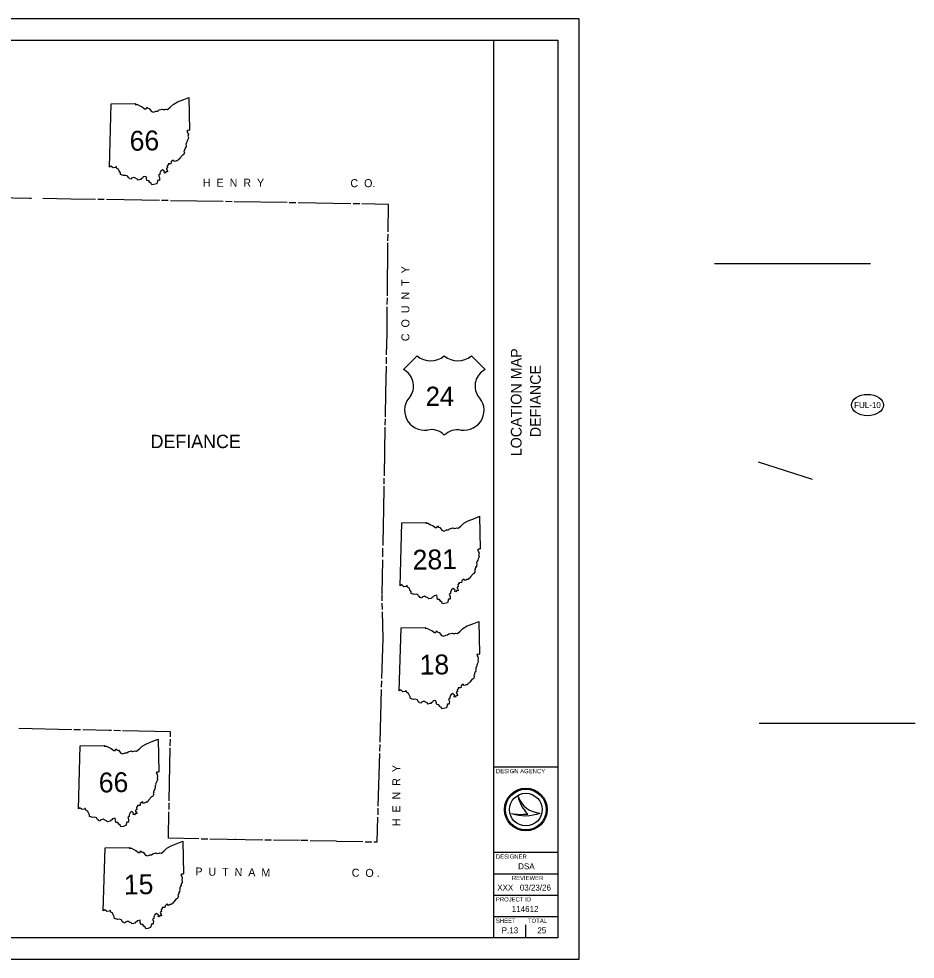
# Model space of a CAD drawing. Extents: x 0 to 419, y 0 to 220.
# Drawn here: x 208.9 to 418.6, y 0 to 220 of the extents above; entities that cross this region are included whole.
import ezdxf

# ---------------------------------------------------------------- set-up
doc = ezdxf.new("R2010")
doc.units = 0
for name, color, linetype in [('GM_X_County', 7, 'Continuous'), ('Level 12', 7, 'Continuous'), ('Level 13', 7, 'Continuous'), ('PV_P_Text', 7, 'Continuous'), ('SH_Border', 7, 'Continuous'), ('SH_Cut_Line', 7, 'Continuous'), ('SH_Data', 7, 'Continuous'), ('SH_Text', 7, 'Continuous')]:
    doc.layers.add(name, color=color, linetype=linetype)

msp = doc.modelspace()

# ---------------------------------------------------------------- linework, layer by layer
at = {"layer": 'GM_X_County'}
for points in [[(211.47, 178), (199.55, 178.2)], [(211.9, 177.99), (211.47, 178)], [(221.09, 177.84), (214.48, 177.95)], [(226.84, 177.74), (221.09, 177.84)], [(228.9, 177.71), (227.36, 177.73)], [(241.78, 177.49), (229.42, 177.7)], [(243.84, 177.46), (242.29, 177.48)], [(256.71, 177.24), (244.36, 177.45)], [(258.78, 177.2), (257.23, 177.23)], [(271.65, 176.99), (259.29, 177.19)], [(273.71, 176.95), (272.16, 176.98)], [(286.58, 176.74), (274.23, 176.94)], [(288.65, 176.7), (287.1, 176.73)], [(295.34, 176.59), (289.16, 176.69)], [(295.27, 170.15), (295.34, 176.59)], [(295.25, 168.08), (295.27, 169.63)], [(295.12, 155.21), (295.25, 167.56)], [(295.1, 153.14), (295.12, 154.69)], [(295.03, 146.45), (295.09, 152.63)], [(294.93, 141.35), (295.03, 146.45)], [(294.9, 139.28), (294.92, 140.83)], [(294.77, 132.59), (294.89, 138.77)], [(294.66, 126.87), (294.77, 132.59)], [(294.63, 124.96), (294.65, 126.39)], [(294.4, 113.05), (294.62, 124.48)], [(294.36, 111.14), (294.39, 112.57)], [(294.25, 104.94), (294.35, 110.66)], [(294.18, 101.71), (294.25, 104.94)], [(294.09, 96.81), (294.18, 101.71)], [(294.04, 94.1), (294.08, 96.14)], [(293.87, 85.29), (294.03, 93.42)], [(293.9, 83.84), (293.87, 85.17)], [(293.95, 81.78), (293.91, 83.33)], [(294.1, 75.08), (293.96, 81.26)], [(293.83, 65.68), (294.1, 75.08)], [(293.77, 63.61), (293.82, 65.16)], [(293.41, 50.74), (293.76, 63.1)], [(221.27, 53.69), (208.91, 53.94)], [(223.33, 53.65), (221.78, 53.68)], [(230.02, 53.52), (223.85, 53.64)], [(230.6, 53.5), (230.02, 53.52)], [(232.66, 53.45), (231.12, 53.49)], [(244.36, 52.02), (244.38, 53.17), (233.18, 53.44)], [(244.32, 49.95), (244.35, 51.5)], [(244.07, 37.08), (244.31, 49.44)], [(293.35, 48.68), (293.39, 50.23)], [(292.98, 35.81), (293.34, 48.16)], [(244.03, 35.02), (244.06, 36.57)], [(292.92, 33.75), (292.97, 35.3)], [(243.91, 28.33), (244.02, 34.5)], [(292.75, 27.44), (292.91, 33.23)], [(251.02, 28.12), (243.91, 28.33)], [(253.08, 28.08), (251.75, 28.1), (251.53, 28.1)], [(265.95, 27.88), (253.6, 28.07)], [(259.51, 28.14), (259.51, 27.98)], [(268, 27.87), (267.69, 27.87), (267.69, 27.86), (266.47, 27.87)], [(274.69, 27.76), (268.51, 27.86)], [(276.5, 27.73), (274.95, 27.76)], [(283.19, 27.63), (277.02, 27.72)], [(283.2, 27.63), (289.38, 27.5)], [(289.89, 27.49), (291.44, 27.46)], [(291.96, 27.45), (292.72, 27.43)]]:
    msp.add_lwpolyline(points, dxfattribs=at)
at = {"layer": 'Level 12'}
for p, q in [((371.6, 162.77), (408.13, 162.77)), ((382.05, 55.19), (418.58, 55.19))]:
    msp.add_line(p, q, dxfattribs=at)
at = {"layer": 'Level 13'}
msp.add_line((394.56, 112.19), (381.94, 116.3), dxfattribs=at)
msp.add_ellipse((407.43, 129.63), major_axis=(3.75, 0), ratio=0.666667, dxfattribs=at)
at = {"layer": 'PV_P_Text'}
for p, q in [((302.08, 141.12), (298.89, 137.92)), ((317.96, 137.92), (314.77, 141.12))]:
    msp.add_line(p, q, dxfattribs=at)
for centre, radius, start, end in [((305.25, 145.15), 5.13, 231.813, 308.187), ((311.59, 145.15), 5.13, 231.813, 308.187), ((296.9, 134.07), 4.34, 329.1175, 62.6108), ((319.95, 134.07), 4.34, 117.3892, 210.8825), ((303.81, 128.42), 4.68, 133.0046, 278.7282), ((313.04, 128.42), 4.68, 261.2718, 46.9954), ((305.38, 119.7), 4.19, 43.4177, 101.8742), ((311.55, 119.42), 4.44, 79.9613, 134.7468)]:
    msp.add_arc(centre, radius, start, end, dxfattribs=at)
at = {"layer": 'SH_Border'}
for p, q in [((320, 5), (320, 215)), ((320, 45), (335, 45)), ((320, 25), (335, 25)), ((320, 20), (335, 20)), ((320, 15), (335, 15)), ((320, 10), (335, 10))]:
    msp.add_line(p, q, dxfattribs=at)
msp.add_lwpolyline([(15, 215), (335, 215), (335, 5), (15, 5)], close=True, dxfattribs=at)
at = {"layer": 'SH_Cut_Line'}
msp.add_lwpolyline([(0, 0), (340, 0), (340, 220), (0, 220)], close=True, dxfattribs=at)
at = {"layer": 'SH_Data'}
for p, q in [((325.67, 38.1), (325.67, 38.1)), ((324.17, 34.1), (324.17, 34.1)), ((327.5, 35), (327.5, 35)), ((330.87, 34.19), (330.87, 34.19)), ((323.75, 6.75), (323.75, 6.75)), ((327.5, 5), (327.5, 8))]:
    msp.add_line(p, q, dxfattribs=at)
for radius in [5, 4.77, 4.77, 3.82]:
    msp.add_circle((327.5, 35), radius, dxfattribs=at)
for centre, radius, start, end in [((331.16, 39.98), 5.8, 198.9257, 198.9319), ((333.47, 39.7), 7.96, 191.6379, 191.6421), ((331.16, 39.98), 5.8, 198.9319, 267.1657), ((333.47, 39.7), 7.96, 191.6421, 226.0947), ((327.39, 43.7), 10.13, 251.4576, 290.0832), ((326.48, 46.54), 12.66, 259.4964, 259.4995), ((327.39, 43.7), 10.13, 251.4527, 251.4576), ((326.48, 46.54), 12.66, 259.4995, 276.6672)]:
    msp.add_arc(centre, radius, start, end, dxfattribs=at)
at = {"layer": 'SH_Text'}
for p, q in [((230.08, 185.33), (230.49, 200.07)), ((298.07, 87.35), (298.48, 102.09)), ((297.89, 62.76), (298.3, 77.49)), ((222.86, 35.2), (223.27, 49.93)), ((228.66, 11.33), (229.07, 26.07))]:
    msp.add_line(p, q, dxfattribs=at)
for points in [[(230.49, 200.07), (236.21, 200.17), (236.12, 199.99), (236.66, 199.95), (237.23, 199.63), (237.72, 199.44), (238.31, 198.97), (238.67, 198.97), (238.82, 199.36), (239.09, 199.06), (239.41, 199.01), (239.97, 198.3), (240.43, 198.15), (240.98, 198.39), (241.39, 198.43), (241.69, 198.67), (242.48, 198.87), (242.69, 198.75), (243.11, 198.78), (243.32, 198.87), (243.68, 198.79), (244.32, 199.32), (244.98, 199.95), (245.99, 200.55), (247.49, 201.11), (248.69, 201.62), (248.86, 193.97)], [(248.86, 193.97), (248.68, 193.86), (248.41, 193.92), (248.22, 193.7), (248.45, 193.34), (248.56, 192.96), (248.46, 192.55), (248.56, 192.2), (248.49, 191.92), (248.32, 191.63), (248.26, 191.36), (248.12, 191.07), (248.13, 190.91), (247.99, 190.78), (248.01, 190.3), (247.94, 190.04), (247.97, 189.81), (247.74, 189.75), (247.79, 189.56), (247.65, 189.41), (247.68, 189.16), (247.52, 189), (247.68, 188.68), (247.55, 188.58), (247.44, 188.19), (247.15, 188.11), (246.57, 187.4), (246.37, 187.13), (246.14, 187.06), (246.01, 186.78), (245.72, 186.78), (245.3, 186.59), (245.02, 186.92), (244.53, 186.52), (244.47, 186.06), (243.86, 186.08), (243.88, 185.85), (243.75, 185.78), (243.62, 185.55), (243.69, 185.13), (243.41, 185.03), (243.44, 184.79), (243.63, 184.64), (243.71, 184.18), (243.4, 184.27), (243.15, 183.89), (242.89, 183.98), (242.98, 184.31), (242.54, 184.7), (242.13, 184.38), (241.91, 183.88), (241.91, 183.54), (241.61, 183.34), (241.8, 182.86), (241.77, 182.53), (241.77, 182.21), (241.39, 182.22), (241.16, 181.38)], [(241.16, 181.38), (240.49, 181.22), (240.03, 181.12), (239.86, 181.5), (239.53, 181.71), (239.32, 182.09), (238.84, 182.15), (238.73, 182.68), (238.67, 183.11), (238.02, 183), (237.85, 182.74), (237.61, 182.67), (237.48, 182.4), (237.17, 182.38), (236.83, 182.25), (236.61, 182.52), (236.06, 182.78), (235.81, 182.91), (235.29, 182.7), (235.18, 182.45), (234.76, 182.56), (234.67, 182.84), (234.42, 182.92), (234.36, 183.22), (233.83, 183.37), (233.42, 183.31), (232.69, 183.55), (232.65, 183.93), (232.4, 184.4), (232.28, 184.73), (231.82, 184.98), (231.73, 185.37), (231.58, 185.36), (231.45, 185.2), (230.94, 185.13), (230.74, 185.29), (230.46, 185.56), (230.08, 185.33)], [(298.48, 102.09), (304.2, 102.19), (304.11, 102.01), (304.65, 101.97), (305.23, 101.65), (305.71, 101.46), (306.3, 100.99), (306.66, 100.99), (306.81, 101.38), (307.08, 101.08), (307.4, 101.03), (307.96, 100.32), (308.42, 100.17), (308.97, 100.41), (309.38, 100.45), (309.68, 100.69), (310.47, 100.89), (310.69, 100.77), (311.1, 100.8), (311.31, 100.89), (311.67, 100.81), (312.31, 101.34), (312.97, 101.97), (313.98, 102.57), (315.49, 103.13), (316.68, 103.64), (316.85, 95.99)], [(316.85, 95.99), (316.67, 95.89), (316.4, 95.94), (316.22, 95.72), (316.44, 95.36), (316.55, 94.99), (316.46, 94.57), (316.55, 94.22), (316.49, 93.94), (316.31, 93.65), (316.25, 93.38), (316.11, 93.09), (316.12, 92.93), (315.98, 92.8), (316.01, 92.32), (315.94, 92.06), (315.96, 91.83), (315.73, 91.77), (315.79, 91.58), (315.64, 91.44), (315.67, 91.18), (315.51, 91.02), (315.67, 90.7), (315.54, 90.6), (315.43, 90.21), (315.14, 90.13), (314.56, 89.42), (314.36, 89.15), (314.13, 89.08), (314, 88.8), (313.72, 88.8), (313.29, 88.61), (313.01, 88.94), (312.52, 88.54), (312.47, 88.08), (311.85, 88.1), (311.88, 87.87), (311.74, 87.8), (311.61, 87.57), (311.69, 87.15), (311.4, 87.05), (311.43, 86.81), (311.62, 86.66), (311.7, 86.2), (311.39, 86.29), (311.14, 85.91), (310.88, 86), (310.97, 86.33), (310.53, 86.72), (310.12, 86.4), (309.91, 85.9), (309.9, 85.56), (309.6, 85.36), (309.79, 84.88), (309.76, 84.55), (309.76, 84.23), (309.38, 84.24), (309.15, 83.4)], [(309.15, 83.4), (308.48, 83.24), (308.02, 83.14), (307.85, 83.52), (307.52, 83.73), (307.31, 84.11), (306.83, 84.17), (306.72, 84.7), (306.67, 85.13), (306.02, 85.02), (305.84, 84.76), (305.61, 84.69), (305.47, 84.42), (305.16, 84.4), (304.82, 84.28), (304.6, 84.54), (304.05, 84.8), (303.8, 84.93), (303.28, 84.72), (303.17, 84.47), (302.75, 84.58), (302.66, 84.86), (302.41, 84.94), (302.35, 85.24), (301.82, 85.39), (301.41, 85.33), (300.69, 85.57), (300.64, 85.95), (300.4, 86.42), (300.27, 86.75), (299.81, 87), (299.72, 87.39), (299.57, 87.38), (299.44, 87.22), (298.93, 87.15), (298.73, 87.31), (298.45, 87.58), (298.07, 87.35)], [(298.3, 77.49), (304.02, 77.59), (303.93, 77.41), (304.47, 77.37), (305.04, 77.06), (305.53, 76.86), (306.12, 76.39), (306.47, 76.4), (306.62, 76.78), (306.9, 76.48), (307.22, 76.43), (307.78, 75.73), (308.24, 75.57), (308.79, 75.81), (309.2, 75.85), (309.5, 76.09), (310.28, 76.3), (310.5, 76.18), (310.92, 76.2), (311.13, 76.29), (311.49, 76.21), (312.13, 76.75), (312.78, 77.38), (313.79, 77.97), (315.3, 78.54), (316.49, 79.04), (316.67, 71.4)], [(316.67, 71.4), (316.49, 71.29), (316.22, 71.34), (316.03, 71.12), (316.26, 70.77), (316.37, 70.39), (316.27, 69.97), (316.37, 69.63), (316.3, 69.34), (316.13, 69.05), (316.07, 68.78), (315.93, 68.49), (315.94, 68.33), (315.8, 68.21), (315.82, 67.73), (315.75, 67.46), (315.78, 67.23), (315.55, 67.17), (315.6, 66.98), (315.46, 66.84), (315.49, 66.59), (315.33, 66.43), (315.48, 66.11), (315.36, 66), (315.25, 65.61), (314.96, 65.54), (314.38, 64.82), (314.17, 64.55), (313.94, 64.48), (313.82, 64.21), (313.53, 64.21), (313.1, 64.01), (312.83, 64.35), (312.34, 63.95), (312.28, 63.49), (311.67, 63.5), (311.69, 63.27), (311.56, 63.2), (311.43, 62.97), (311.5, 62.56), (311.21, 62.45), (311.25, 62.21), (311.43, 62.06), (311.52, 61.6), (311.21, 61.7), (310.96, 61.31), (310.7, 61.4), (310.79, 61.73), (310.35, 62.12), (309.94, 61.81), (309.72, 61.3), (309.72, 60.96), (309.41, 60.76), (309.61, 60.28), (309.57, 59.95), (309.58, 59.64), (309.2, 59.65), (308.96, 58.8)], [(308.96, 58.8), (308.3, 58.64), (307.83, 58.54), (307.67, 58.93), (307.34, 59.13), (307.12, 59.52), (306.65, 59.57), (306.54, 60.1), (306.48, 60.53), (305.83, 60.43), (305.65, 60.16), (305.42, 60.09), (305.29, 59.83), (304.97, 59.8), (304.64, 59.68), (304.42, 59.94), (303.86, 60.2), (303.62, 60.34), (303.1, 60.13), (302.98, 59.88), (302.57, 59.99), (302.47, 60.26), (302.22, 60.35), (302.17, 60.64), (301.63, 60.8), (301.22, 60.73), (300.5, 60.97), (300.46, 61.36), (300.21, 61.83), (300.08, 62.15), (299.63, 62.4), (299.54, 62.79), (299.39, 62.78), (299.26, 62.62), (298.75, 62.55), (298.55, 62.71), (298.26, 62.98), (297.89, 62.76)], [(223.27, 49.93), (228.99, 50.03), (228.9, 49.85), (229.44, 49.81), (230.01, 49.5), (230.5, 49.3), (231.09, 48.83), (231.44, 48.84), (231.59, 49.22), (231.87, 48.92), (232.19, 48.87), (232.75, 48.17), (233.21, 48.01), (233.76, 48.25), (234.17, 48.29), (234.47, 48.53), (235.25, 48.74), (235.47, 48.61), (235.89, 48.64), (236.1, 48.73), (236.46, 48.65), (237.1, 49.18), (237.75, 49.82), (238.76, 50.41), (240.27, 50.98), (241.47, 51.48), (241.64, 43.84)], [(241.64, 43.84), (241.46, 43.73), (241.19, 43.78), (241, 43.56), (241.23, 43.21), (241.34, 42.83), (241.24, 42.41), (241.34, 42.07), (241.27, 41.78), (241.1, 41.49), (241.04, 41.22), (240.9, 40.93), (240.91, 40.77), (240.77, 40.65), (240.79, 40.17), (240.72, 39.9), (240.75, 39.67), (240.52, 39.61), (240.57, 39.42), (240.43, 39.28), (240.46, 39.03), (240.3, 38.87), (240.45, 38.55), (240.33, 38.44), (240.22, 38.05), (239.93, 37.98), (239.35, 37.26), (239.14, 36.99), (238.91, 36.92), (238.79, 36.65), (238.5, 36.65), (238.07, 36.45), (237.8, 36.78), (237.31, 36.39), (237.25, 35.93), (236.64, 35.94), (236.66, 35.71), (236.53, 35.64), (236.4, 35.41), (236.47, 35), (236.19, 34.89), (236.22, 34.65), (236.4, 34.5), (236.49, 34.04), (236.18, 34.14), (235.93, 33.75), (235.67, 33.84), (235.76, 34.17), (235.32, 34.56), (234.91, 34.25), (234.69, 33.74), (234.69, 33.4), (234.38, 33.2), (234.58, 32.72), (234.55, 32.39), (234.55, 32.08), (234.17, 32.09), (233.93, 31.24)], [(233.93, 31.24), (233.27, 31.08), (232.8, 30.98), (232.64, 31.37), (232.31, 31.57), (232.09, 31.96), (231.62, 32.01), (231.51, 32.54), (231.45, 32.97), (230.8, 32.87), (230.62, 32.6), (230.39, 32.53), (230.26, 32.27), (229.95, 32.24), (229.61, 32.12), (229.39, 32.38), (228.83, 32.64), (228.59, 32.78), (228.07, 32.57), (227.96, 32.32), (227.54, 32.43), (227.44, 32.7), (227.19, 32.79), (227.14, 33.08), (226.6, 33.24), (226.2, 33.17), (225.47, 33.41), (225.43, 33.8), (225.18, 34.27), (225.06, 34.59), (224.6, 34.84), (224.51, 35.23), (224.36, 35.22), (224.23, 35.06), (223.72, 34.99), (223.52, 35.15), (223.23, 35.42), (222.86, 35.2)], [(229.07, 26.07), (234.79, 26.16), (234.7, 25.98), (235.24, 25.95), (235.81, 25.63), (236.3, 25.43), (236.89, 24.96), (237.25, 24.97), (237.4, 25.35), (237.67, 25.06), (237.99, 25), (238.55, 24.3), (239.01, 24.15), (239.56, 24.39), (239.97, 24.43), (240.27, 24.67), (241.06, 24.87), (241.27, 24.75), (241.69, 24.77), (241.9, 24.86), (242.26, 24.78), (242.9, 25.32), (243.56, 25.95), (244.57, 26.55), (246.07, 27.11), (247.27, 27.62), (247.44, 19.97)], [(247.44, 19.97), (247.26, 19.86), (246.99, 19.91), (246.8, 19.7), (247.03, 19.34), (247.14, 18.96), (247.04, 18.55), (247.14, 18.2), (247.07, 17.91), (246.9, 17.63), (246.84, 17.35), (246.7, 17.07), (246.71, 16.91), (246.57, 16.78), (246.59, 16.3), (246.52, 16.04), (246.55, 15.81), (246.32, 15.75), (246.37, 15.56), (246.23, 15.41), (246.26, 15.16), (246.1, 15), (246.26, 14.68), (246.13, 14.58), (246.02, 14.19), (245.73, 14.11), (245.15, 13.4), (244.95, 13.13), (244.72, 13.06), (244.59, 12.78), (244.3, 12.78), (243.88, 12.59), (243.6, 12.92), (243.11, 12.52), (243.06, 12.06), (242.44, 12.08), (242.46, 11.84), (242.33, 11.78), (242.2, 11.54), (242.27, 11.13), (241.99, 11.02), (242.02, 10.78), (242.21, 10.64), (242.29, 10.18), (241.98, 10.27), (241.73, 9.88), (241.47, 9.98), (241.56, 10.3), (241.12, 10.7), (240.71, 10.38), (240.5, 9.88), (240.49, 9.54), (240.19, 9.33), (240.38, 8.85), (240.35, 8.52), (240.35, 8.21), (239.97, 8.22), (239.74, 7.38)], [(239.74, 7.38), (239.07, 7.21), (238.61, 7.12), (238.44, 7.5), (238.11, 7.7), (237.9, 8.09), (237.42, 8.14), (237.31, 8.67), (237.25, 9.11), (236.6, 9), (236.43, 8.74), (236.19, 8.67), (236.06, 8.4), (235.75, 8.38), (235.41, 8.25), (235.19, 8.51), (234.64, 8.77), (234.39, 8.91), (233.87, 8.7), (233.76, 8.45), (233.34, 8.56), (233.25, 8.84), (233, 8.92), (232.94, 9.21), (232.41, 9.37), (232, 9.31), (231.27, 9.54), (231.23, 9.93), (230.98, 10.4), (230.86, 10.73), (230.4, 10.98), (230.31, 11.37), (230.16, 11.35), (230.03, 11.2), (229.52, 11.12), (229.32, 11.28), (229.04, 11.55), (228.66, 11.33)]]:
    msp.add_lwpolyline(points, dxfattribs=at)

# ---------------------------------------------------------------- texts
at = {"layer": 'Level 13'}
msp.add_text('FUL-10', height=1.4, dxfattribs=at).set_placement((404.3, 128.93))
at = {"layer": 'PV_P_Text'}
msp.add_text('24', height=4.489, dxfattribs=at).set_placement((304.06, 129.45))
at = {"layer": 'SH_Data'}
for s, p in [('LOCATION MAP', (326.5, 117.65)), ('DEFIANCE', (331, 122.11))]:
    msp.add_text(s, height=2.5, rotation=90, dxfattribs=at).set_placement(p)
for s, height, p in [('DESIGN AGENCY', 1, (320.5, 43.5)), ('DESIGNER', 1, (320.5, 23.5)), ('DSA', 1.4, (325.7, 21.05)), ('REVIEWER', 1, (324.22, 18.5)), ('XXX', 1.4, (320.81, 16.05)), ('03/23/26', 1.4, (326.09, 16.05)), ('PROJECT ID', 1, (320.5, 13.5)), ('114612', 1.4, (324.21, 11.05)), ('SHEET', 1, (320.5, 8.5)), ('TOTAL', 1, (328, 8.5)), ('P.13', 1.4, (321.85, 6.05)), ('25', 1.4, (330.2, 6.05))]:
    msp.add_text(s, height=height, dxfattribs=at).set_placement(p)
at = {"layer": 'SH_Text'}
for s, height, rotation, p in [('66', 4.646, 1.0142, (234.86, 189.12)), ('H  E  N  R  Y', 1.8731, 0.0369, (251.95, 180.7)), ('C  O.', 1.873, 0.0407, (286.47, 180.61)), ('C  O  U  N  T  Y', 1.8734, 90.0407, (300.26, 144.59)), ('DEFIANCE', 3.122, 0.0349, (239.72, 119.56)), ('281', 4.646, 1.0142, (301.06, 91.11)), ('18', 4.646, 1.0142, (302.68, 66.55)), ('H  E  N  R  Y', 1.8727, 90.0282, (298.14, 31.1)), ('66', 4.646, 1.0142, (227.64, 38.99)), ('15', 4.646, 1.0142, (233.51, 15.12)), ('P  U  T  N  A  M', 1.8729, 359.1344, (250.18, 19.59)), ('C  O .', 1.873, 359.1456, (286.76, 19.31))]:
    msp.add_text(s, height=height, rotation=rotation, dxfattribs=at).set_placement(p)

doc.saveas('drawing.dxf')
